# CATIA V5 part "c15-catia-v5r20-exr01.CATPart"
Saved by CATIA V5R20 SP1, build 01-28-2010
Part number: Part1
Bounding box of the stored display mesh (mm): x -80 to 10, y -30 to 1, z 0 to 35
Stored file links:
  D:\v5_r20\psrt_files_downloaded\c15\c15-catia-v5r20-exr01.CATPart
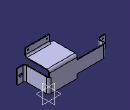
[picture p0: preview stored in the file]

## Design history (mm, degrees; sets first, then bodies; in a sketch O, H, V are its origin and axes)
SheetMetalParameters1: Thickness 1, BendRadius 2, KFactor 0.400515 {= log(min(100,max(20*SheetMetalParameters1.BendRadius,SheetMetalParameters1.Thickness)/SheetMetalParameters1.Thickness))/log(100)/2}, ReliefRadialLength 1, ReliefAxialLength 2, MinimumBendRadius 0
Body1 (main body)
  Sketch1 on zx-plane, origin (0, 0, 0), H (-1, 0, 0), V (0, 0, 1)
    line L1 (0, 0) -> (35, 0)
    line L2 (35, 0) -> (35, 5)
    line L3 (35, 5) -> (70, 5)
    line L4 (70, 5) -> (70, 20)
    line L5 (70, 20) -> (35, 20)
    line L6 (0, 0) -> (0, 25)
    line L7 (0, 25) -> (35, 25)
    point P7 (35, 25)
    line L8 (35, 25) -> (35, 20)
    length L4 = 15
    distance L1 L3 = 5
    length L6 = 25
    length L7 = 35
    length L5 = 35
    horizontal: L1 H, L3 H, L5 H, L7 H
    vertical: L4 V, L2 V, L8 V, L6 V
    coincidence: P7 L2
  Wall1: Thickness 1, Profile Sketch1
  d_NewWallOnEdge1: NewWallOnEdge_Edge edge [face of Wall1 | face of Wall1], NewWallOnEdge_Length 30, NewWallOnEdge_HeightLimitOffset 0, NewWallOnEdge_WidthOffset1 0, NewWallOnEdge_WidthOffset2 0, NewWallOnEdge_Angle 90, NewWallOnEdge_BendRadiusValue 2 {= SheetMetalParameters1.BendRadius}, NewWallOnEdge_BendTable SheetMetalParameters1, KFacteur 0.400515 {= log(min(100,max(20*d_NewWallOnEdge1.Radius,SheetMetalParameters1.Thickness)/SheetMetalParameters1.Thickness))/log(100)/2}
  d_NewWallOnEdge2: NewWallOnEdge_Edge edge [face of Wall1 | face of Wall1], NewWallOnEdge_Length 10, NewWallOnEdge_HeightLimitOffset 0, NewWallOnEdge_WidthOffset1 0, NewWallOnEdge_WidthOffset2 0, NewWallOnEdge_Angle 90, NewWallOnEdge_BendRadiusValue 2 {= SheetMetalParameters1.BendRadius}, NewWallOnEdge_BendTable SheetMetalParameters1, KFacteur 0.400515 {= log(min(100,max(20*d_NewWallOnEdge2.Radius,SheetMetalParameters1.Thickness)/SheetMetalParameters1.Thickness))/log(100)/2}
  d_NewWallOnEdge3: NewWallOnEdge_Edge edge [face of Wall1 | face of Wall1], NewWallOnEdge_Length 30, NewWallOnEdge_HeightLimitOffset 0, NewWallOnEdge_WidthOffset1 0, NewWallOnEdge_WidthOffset2 -5, NewWallOnEdge_Angle 90, NewWallOnEdge_BendRadiusValue 2 {= SheetMetalParameters1.BendRadius}, NewWallOnEdge_BendTable SheetMetalParameters1, KFacteur 0.400515 {= log(min(100,max(20*d_NewWallOnEdge3.Radius,SheetMetalParameters1.Thickness)/SheetMetalParameters1.Thickness))/log(100)/2}
  d_NewWallOnEdge4: NewWallOnEdge_Edge edge [face of d_NewWallOnEdge3 | face of d_NewWallOnEdge3], NewWallOnEdge_Length 10, NewWallOnEdge_HeightLimitOffset 0, NewWallOnEdge_WidthOffset1 0, NewWallOnEdge_WidthOffset2 0, NewWallOnEdge_Angle 90, NewWallOnEdge_BendRadiusValue 2 {= SheetMetalParameters1.BendRadius}, NewWallOnEdge_BendTable SheetMetalParameters1, KFacteur 0.400515 {= log(min(100,max(20*d_NewWallOnEdge4.Radius,SheetMetalParameters1.Thickness)/SheetMetalParameters1.Thickness))/log(100)/2}
  d_NewWallOnEdge5: NewWallOnEdge_Edge edge [face of d_NewWallOnEdge1 | face of d_NewWallOnEdge1], NewWallOnEdge_Length 10, NewWallOnEdge_HeightLimitOffset 0, NewWallOnEdge_WidthOffset1 -5, NewWallOnEdge_WidthOffset2 0, NewWallOnEdge_Angle 90, NewWallOnEdge_BendRadiusValue 2 {= SheetMetalParameters1.BendRadius}, NewWallOnEdge_BendTable SheetMetalParameters1, KFacteur 0.400515 {= log(min(100,max(20*d_NewWallOnEdge5.Radius,SheetMetalParameters1.Thickness)/SheetMetalParameters1.Thickness))/log(100)/2}
  d_NewWallOnEdge6: NewWallOnEdge_Edge edge [face of d_NewWallOnEdge2 | face of d_NewWallOnEdge2], NewWallOnEdge_Length 10, NewWallOnEdge_HeightLimitOffset 0, NewWallOnEdge_WidthOffset1 0, NewWallOnEdge_WidthOffset2 0, NewWallOnEdge_Angle 90, NewWallOnEdge_BendRadiusValue 2 {= SheetMetalParameters1.BendRadius}, NewWallOnEdge_BendTable SheetMetalParameters1, KFacteur 0.400515 {= log(min(100,max(20*d_NewWallOnEdge6.Radius,SheetMetalParameters1.Thickness)/SheetMetalParameters1.Thickness))/log(100)/2}
  Sketch2 on face of d_NewWallOnEdge4, origin (6.9396, -29, 15.1305), H (1, 0, 0), V (0, 0, -1)
    point P1 (-0.9396, 6.1305)
    reference projected line E1 (3.0604, 10.1305) -> (3.0604, -7.8695) from edge [face of d_NewWallOnEdge4 | face of d_NewWallOnEdge4]
    reference projected line E2 (3.0604, -2.8695) -> (-3.9396, -2.8695) from edge [face of d_NewWallOnEdge4 | face of d_NewWallOnEdge4]
    distance P1 E1 = 4
    distance P1 E2 = 9
  Hole1: placed by Sketch2, at (6, -29, 9) direction (0, -1, 0), diameter 4, through (limit type 6)
  Sketch3 on face of d_NewWallOnEdge6, origin (-77.3716, -9, 10.6324), H (1, 0, 0), V (0, 0, -1)
    point P1 (0.3716, 2.6324)
    reference projected line E1 (-2.6284, 5.6324) -> (4.3716, 5.6324) from edge [face of d_NewWallOnEdge6 | face of d_NewWallOnEdge6]
    reference projected line E2 (-2.6284, -9.3676) -> (-2.6284, 5.6324) from edge [face of d_NewWallOnEdge6 | face of d_NewWallOnEdge6]
    distance P1 E1 = 3
    distance P1 E2 = 3
  Hole2: placed by Sketch3, at (-77, -9, 8) direction (0, -1, 0), diameter 2, through (limit type 6)
  Sketch4 on face of d_NewWallOnEdge6, origin (-77.6837, -9, 16.1337), H (1, 0, 0), V (0, 0, -1)
    point P1 (0.6837, -0.8663)
    reference projected line E1 (4.6837, -3.8663) -> (-2.3163, -3.8663) from edge [face of d_NewWallOnEdge6 | face of d_NewWallOnEdge6]
    reference projected line E2 (-2.3163, -3.8663) -> (-2.3163, 11.1337) from edge [face of d_NewWallOnEdge6 | face of d_NewWallOnEdge6]
    distance E1 P1 = 3
    distance P1 E2 = 3
  Hole3: placed by Sketch4, at (-77, -9, 17) direction (0, -1, 0), diameter 2, through (limit type 6)
  Sketch5 on face of d_NewWallOnEdge5, origin (-17.5157, -29, 32.087), H (1, 0, 0), V (0, 0, -1)
    point P1 (-9.4843, 0.087)
    reference projected line E1 (17.5157, -2.913) -> (-12.4843, -2.913) from edge [face of d_NewWallOnEdge5 | face of d_NewWallOnEdge5]
    reference projected line E2 (-12.4843, -2.913) -> (-12.4843, 4.087) from edge [face of d_NewWallOnEdge5 | face of d_NewWallOnEdge5]
    distance E1 P1 = 3
    distance E2 P1 = 3
  Hole4: placed by Sketch5, at (-27, -29, 32) direction (0, -1, 0), diameter 2, through (limit type 6)
  Sketch6 on face of d_NewWallOnEdge5, origin (-4.3141, -29, 29.8473), H (1, 0, 0), V (0, 0, -1)
    point P1 (1.3141, -2.1527)
    reference projected line E1 (4.3141, 1.8473) -> (4.3141, -5.1527) from edge [face of d_NewWallOnEdge5 | face of d_NewWallOnEdge5]
    reference projected line E2 (4.3141, -5.1527) -> (-25.6859, -5.1527) from edge [face of d_NewWallOnEdge5 | face of d_NewWallOnEdge5]
    distance P1 E1 = 3
    distance P1 E2 = 3
  Hole5: placed by Sketch6, at (-3, -29, 32) direction (0, -1, 0), diameter 2, through (limit type 6)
